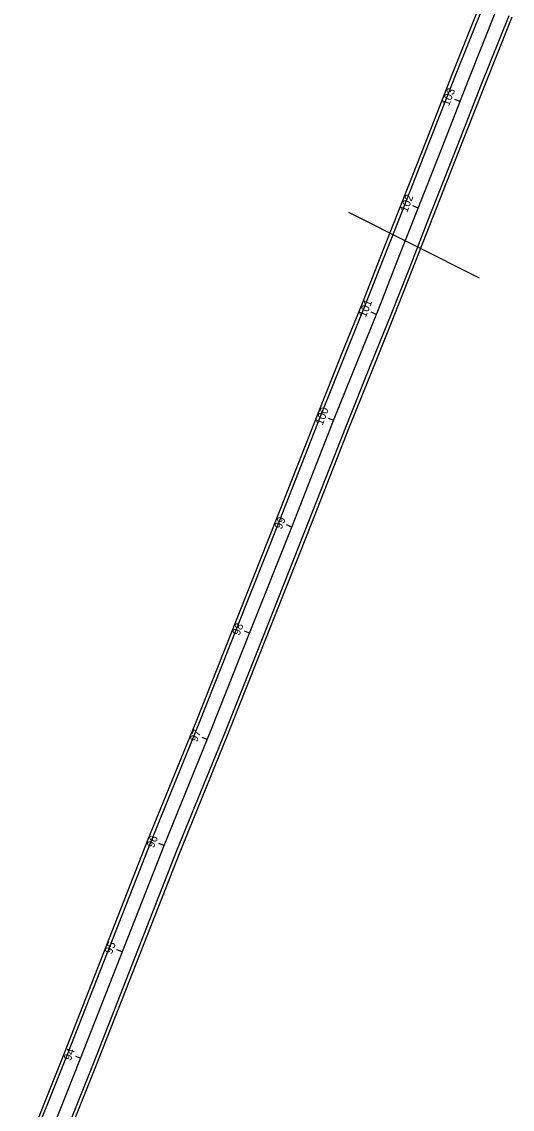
# Model space of a CAD drawing. Extents: x 2318076 to 2324211, y 613525 to 629939.
# Drawn here: x 2319749 to 2320178, y 624026 to 624977 of the extents above; entities that cross this region are included whole.
import ezdxf

# ---------------------------------------------------------------- set-up
doc = ezdxf.new("R2010")
doc.units = 0
for name, color, linetype in [('DR_P_Culvert', 7, 'Continuous'), ('GE_P_CL_50', 7, 'Continuous'), ('PV_P_EOP', 7, 'Continuous'), ('PV_P_Shoulder', 7, 'Continuous')]:
    doc.layers.add(name, color=color, linetype=linetype)

msp = doc.modelspace()

# ---------------------------------------------------------------- linework, layer by layer
at = {"layer": 'DR_P_Culvert'}
msp.add_line((2320034.83, 624810.3), (2320149.17, 624752.68), dxfattribs=at)
at = {"layer": 'GE_P_CL_50'}
for p, q in [((2320132.42, 624906.88), (2320127.77, 624908.71)), ((2320095.86, 624813.81), (2320091.21, 624815.64)), ((2320059.27, 624720.74), (2320054.64, 624722.63)), ((2320021.98, 624627.96), (2320017.31, 624629.76)), ((2319985.34, 624534.91), (2319980.7, 624536.78)), ((2319948.42, 624441.98), (2319943.77, 624443.82)), ((2319911.43, 624349.07), (2319906.8, 624350.95)), ((2319873.66, 624256.48), (2319869, 624258.31)), ((2319836.84, 624163.51), (2319832.21, 624165.38)), ((2319800.93, 624070.19), (2319796.29, 624072.07))]:
    msp.add_line(p, q, dxfattribs=at)
msp.add_lwpolyline([(2319763.02, 623976.24), (2319800.59, 624070.33), (2319873.66, 624256.48), (2319915.47, 624359.03), (2319948.42, 624441.98), (2319985.34, 624534.91), (2320021.89, 624627.99), (2320043.28, 624681.47), (2320061.02, 624725.04), (2320076.64, 624764.88), (2320092.61, 624805.53), (2320116.67, 624866.77), (2320140.16, 624926.58), (2320164.06, 624986.38)], dxfattribs=at)
at = {"layer": 'PV_P_EOP'}
for points in [[(2319751.86, 623980.66), (2319789.43, 624074.75), (2319862.52, 624260.94), (2319904.34, 624363.51), (2319937.27, 624446.41), (2319974.18, 624539.32), (2320010.73, 624632.41), (2320032.15, 624685.96), (2320049.88, 624729.49), (2320065.47, 624769.26), (2320081.44, 624809.92), (2320105.5, 624871.16), (2320129, 624931), (2320152.83, 624990.62)], [(2319774.18, 623971.82), (2319811.75, 624065.91), (2319884.8, 624252.03), (2319926.6, 624354.55), (2319959.57, 624437.55), (2319996.5, 624530.51), (2320033.04, 624623.57), (2320054.41, 624676.98), (2320072.16, 624720.59), (2320087.81, 624760.5), (2320103.78, 624801.14), (2320127.84, 624862.38), (2320151.32, 624922.16), (2320175.29, 624982.14)]]:
    msp.add_lwpolyline(points, dxfattribs=at)
at = {"layer": 'PV_P_Shoulder'}
for points in [[(2319749.07, 623981.77), (2319786.64, 624075.85), (2319859.73, 624262.06), (2319901.55, 624364.63), (2319971.39, 624540.43), (2320007.94, 624633.52), (2320029.37, 624687.08), (2320047.09, 624730.61), (2320062.68, 624770.36), (2320102.71, 624872.25), (2320126.21, 624932.11), (2320150.02, 624991.68)], [(2319776.97, 623970.71), (2319814.54, 624064.81), (2319887.58, 624250.91), (2319929.39, 624353.43), (2319999.29, 624529.4), (2320035.83, 624622.47), (2320057.19, 624675.86), (2320074.95, 624719.47), (2320090.6, 624759.4), (2320130.63, 624861.29), (2320154.11, 624921.05), (2320178.1, 624981.08)]]:
    msp.add_lwpolyline(points, dxfattribs=at)

# ---------------------------------------------------------------- texts
at = {"layer": 'GE_P_CL_50'}
for s, rotation, p in [('103', 68.5579, (2320122.62, 624902.44)), ('102', 68.55111, (2320086.09, 624809.45)), ('101', 67.84577, (2320049.88, 624717.58)), ('100', 68.93858, (2320012.18, 624623.38)), ('99', 68.04407, (2319976.24, 624532.4)), ('98', 68.38168, (2319939.38, 624439.52)), ('97', 67.93058, (2319902.26, 624346.4)), ('96', 68.54557, (2319864.56, 624253.84)), ('95', 67.99652, (2319827.73, 624160.98)), ('94', 67.99549, (2319791.85, 624067.74))]:
    msp.add_text(s, height=7, rotation=rotation, dxfattribs=at).set_placement(p)

doc.saveas('drawing.dxf')
